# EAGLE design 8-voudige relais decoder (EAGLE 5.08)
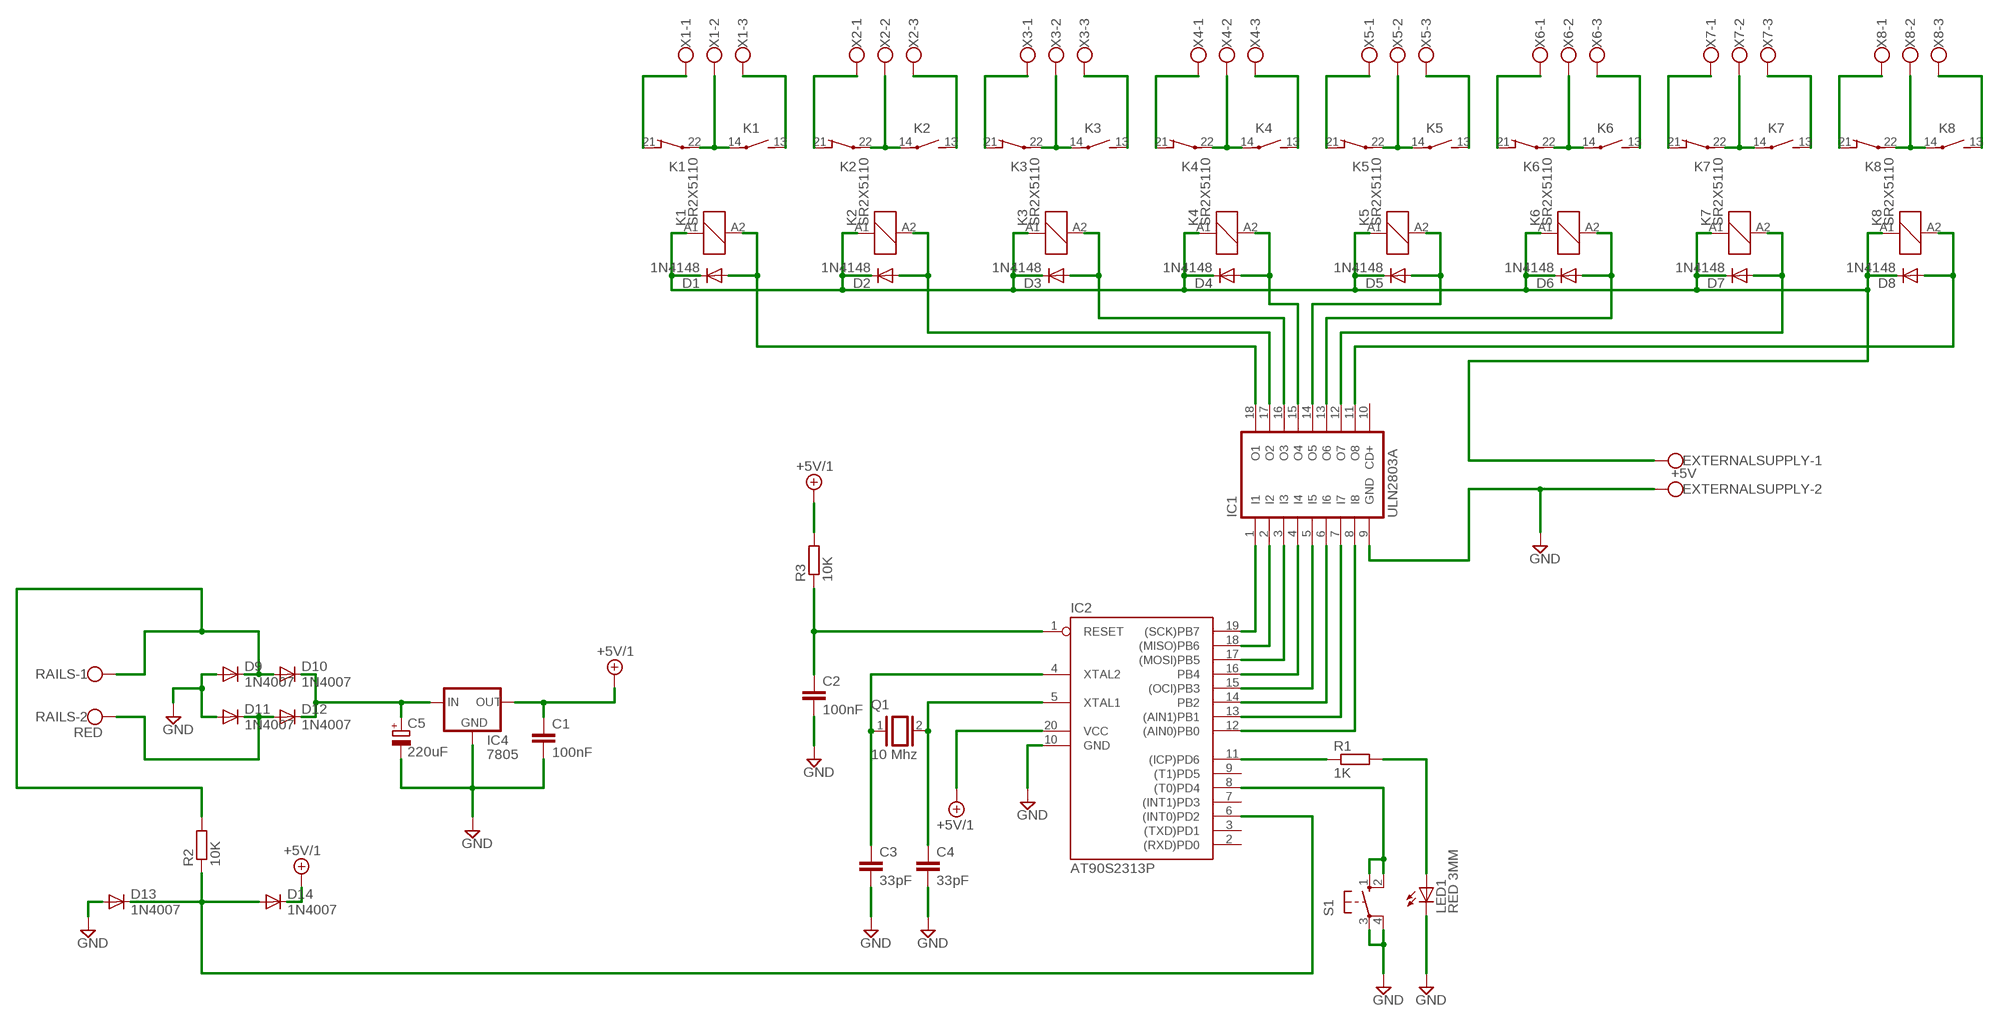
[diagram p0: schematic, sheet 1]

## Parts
C1  100nF  C-EU025-025X050  [C025-025X050]
C2  100nF  C-EU025-025X050  [C025-025X050]
C3  33pF  C-EU025-025X050  [C025-025X050]
C4  33pF  C-EU025-025X050  [C025-025X050]
C5  220uF  CPOL-EUTT6D6  [TT5D6]
D1  1N4148  1N4148DO35-7  [DO35-7]
D2  1N4148  1N4148DO35-7  [DO35-7]
D3  1N4148  1N4148DO35-7  [DO35-7]
D4  1N4148  1N4148DO35-7  [DO35-7]
D5  1N4148  1N4148DO35-7  [DO35-7]
D6  1N4148  1N4148DO35-7  [DO35-7]
D7  1N4148  1N4148DO35-7  [DO35-7]
D8  1N4148  1N4148DO35-7  [DO35-7]
D9  1N4007  1N4148DO35-10  [DO35-10]
D10  1N4007  1N4148DO35-10  [DO35-10]
D11  1N4007  1N4148DO35-10  [DO35-10]
D12  1N4007  1N4148DO35-10  [DO35-10]
D13  1N4007  1N4148DO35-10  [DO35-10]
D14  1N4007  1N4148DO35-10  [DO35-10]
EXTERNALSUPPLY  +5V  W237-102  [W237-102]
IC1  ULN2803A  [DIL18]
IC2  AT90S2313P  [DIL20]
IC4  7805  78XXL  [78XXL]
K1  SR2X5110  [SR2X]
K2  SR2X5110  [SR2X]
K3  SR2X5110  [SR2X]
K4  SR2X5110  [SR2X]
K5  SR2X5110  [SR2X]
K6  SR2X5110  [SR2X]
K7  SR2X5110  [SR2X]
K8  SR2X5110  [SR2X]
LED1  RED 3MM  LED3MM  [LED3MM]
Q1  10 Mhz  XTAL/S  [QS]
R1  1K  R-EU_0207/10  [0207/10]
R2  10K  R-EU_0207/10  [0207/10]
R3  10K  R-EU_0207/10  [0207/10]
RAILS  RED  W237-102  [W237-102]
S1  10-XX  [B3F-10XX]
X1  W237-103  [W237-103]
X2  W237-103  [W237-103]
X3  W237-103  [W237-103]
X4  W237-103  [W237-103]
X5  W237-103  [W237-103]
X6  W237-103  [W237-103]
X7  W237-103  [W237-103]
X8  W237-103  [W237-103]

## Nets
+5V/1: C1.1 D14.C IC2.20(VCC) IC4.OUT R3.2
GND: C1.2 C2.2 C3.2 C4.2 C5.- D9.A D11.A D13.A EXTERNALSUPPLY.2 IC1.9(GND) IC2.10(GND) IC4.GND LED1.K(C) S1.3(P) S1.4(P1)
N$1: D1.C D2.C D3.C D4.C D5.C D6.C D7.C D8.C EXTERNALSUPPLY.1 K1.A1 K2.A1 K3.A1 K4.A1 K5.A1 K6.A1 K7.A1 K8.A1
N$2: D1.A IC1.18(O1) K1.A2
N$3: K1.14(3:P) K1.22(2:P) X1.2
N$4: D2.A IC1.17(O2) K2.A2
N$5: K2.14(3:P) K2.22(2:P) X2.2
N$6: D3.A IC1.16(O3) K3.A2
N$7: K3.14(3:P) K3.22(2:P) X3.2
N$8: D4.A IC1.15(O4) K4.A2
N$9: K4.14(3:P) K4.22(2:P) X4.2
N$10: D5.A IC1.14(O5) K5.A2
N$11: K5.14(3:P) K5.22(2:P) X5.2
N$12: D6.A IC1.13(O6) K6.A2
N$13: K6.14(3:P) K6.22(2:P) X6.2
N$14: D7.A IC1.12(O7) K7.A2
N$15: K7.14(3:P) K7.22(2:P) X7.2
N$16: D8.A IC1.11(O8) K8.A2
N$17: K8.14(3:P) K8.22(2:P) X8.2
N$18: K1.21(2:O) X1.1
N$19: K1.13(3:S) X1.3
N$20: K2.21(2:O) X2.1
N$21: K2.13(3:S) X2.3
N$22: K3.21(2:O) X3.1
N$23: K3.13(3:S) X3.3
N$24: K4.21(2:O) X4.1
N$25: K4.13(3:S) X4.3
N$26: K5.21(2:O) X5.1
N$27: K5.13(3:S) X5.3
N$28: K6.21(2:O) X6.1
N$29: K6.13(3:S) X6.3
N$30: K7.21(2:O) X7.1
N$31: K7.13(3:S) X7.3
N$32: K8.21(2:O) X8.1
N$33: K8.13(3:S) X8.3
N$34: IC1.1(I1) IC2.19((SCK)PB7)
N$35: IC1.2(I2) IC2.18((MISO)PB6)
N$36: IC1.3(I3) IC2.17((MOSI)PB5)
N$37: IC1.4(I4) IC2.16(PB4)
N$38: IC1.5(I5) IC2.15((OCI)PB3)
N$39: IC1.6(I6) IC2.14(PB2)
N$40: IC1.7(I7) IC2.13((AIN1)PB1)
N$41: IC1.8(I8) IC2.12((AIN0)PB0)
N$42: IC2.8((T0)PD4) S1.1(S) S1.2(S1)
N$43: C4.1 IC2.5(XTAL1) Q1.2
N$44: IC2.11((ICP)PD6) R1.1
N$45: LED1.A R1.2
N$46: D13.C D14.A IC2.6((INT0)PD2) R2.1
N$47: C5.+ D10.C D12.C IC4.IN
N$48: D9.C D10.A R2.2 RAILS.1
N$49: D11.C D12.A RAILS.2
N$50: C3.1 IC2.4(XTAL2) Q1.1
N$51: C2.1 IC2.1(RESET) R3.1
Unconnected: IC1.10(CD+) IC2.2((RXD)PD0) IC2.3((TXD)PD1) IC2.7((INT1)PD3) IC2.9((T1)PD5)

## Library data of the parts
C1-C4 = rcl:C-EU: CAPACITOR, European symbol
C5 = rcl:CPOL-EU: POLARIZED CAPACITOR, European symbol
D1-D14 = diode:1N4148: DIODE
EXTERNALSUPPLY RAILS = con-wago-500:W237-102: WAGO SCREW CLAMP
IC1 = uln-udn:ULN2803A: DRIVER ARRAY
IC2 = atmel:AT90S2313: MICROCONTROLLER 2 Kbytes FLASH 128 bytes SRAM 128 bytes EEPROM UART
IC4 = v-reg:78XXL: VOLTAGE REGULATOR
K1-K8 = relay:SR2X5*: Safety Relay 2 pole 6 A SCHRACK Source: http://www.schrack.com/.. 5809.pdf
LED1 = led:LED: LED
Q1 = special:XTAL/S: CRYSTAL
R1-R3 = resistor:R-EU_: RESISTOR, European symbol
S1 = switch-omron:10-XX: OMRON SWITCH
X1-X8 = con-wago-500:W237-103: WAGO SCREW CLAMP

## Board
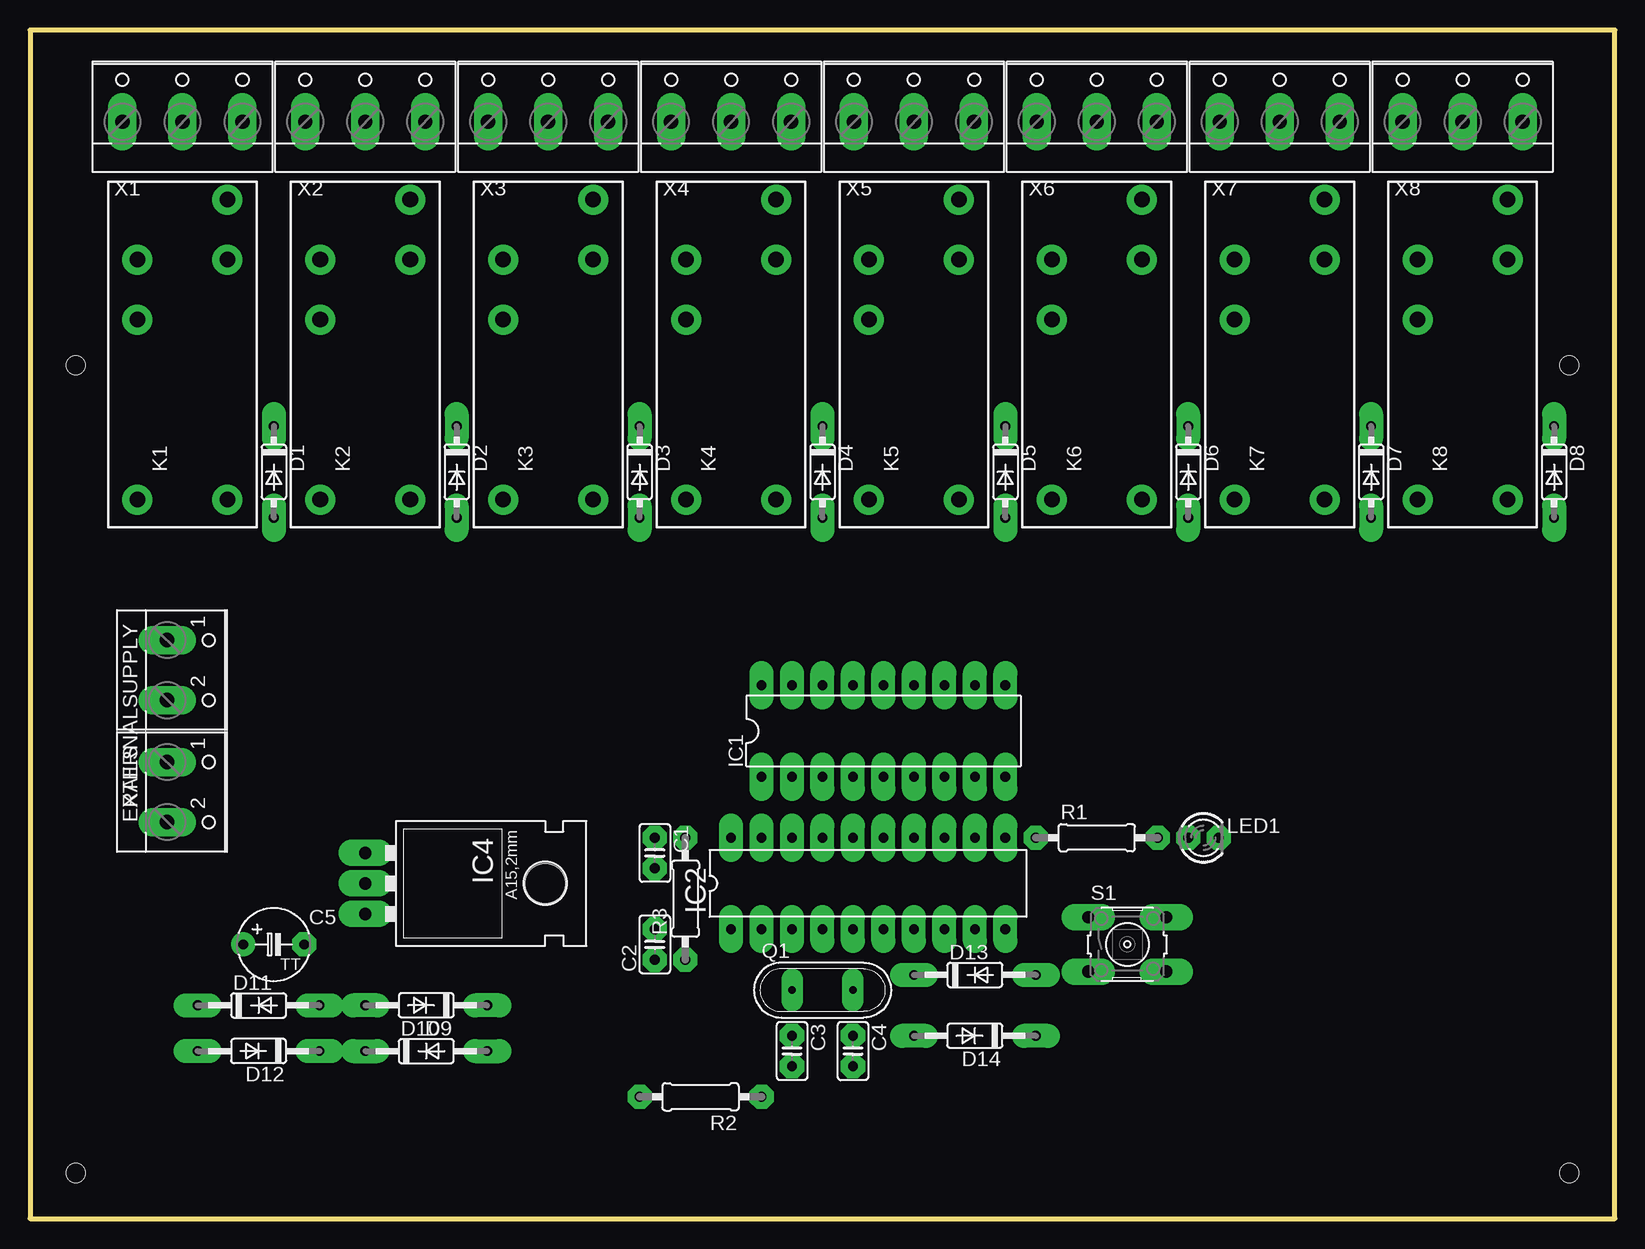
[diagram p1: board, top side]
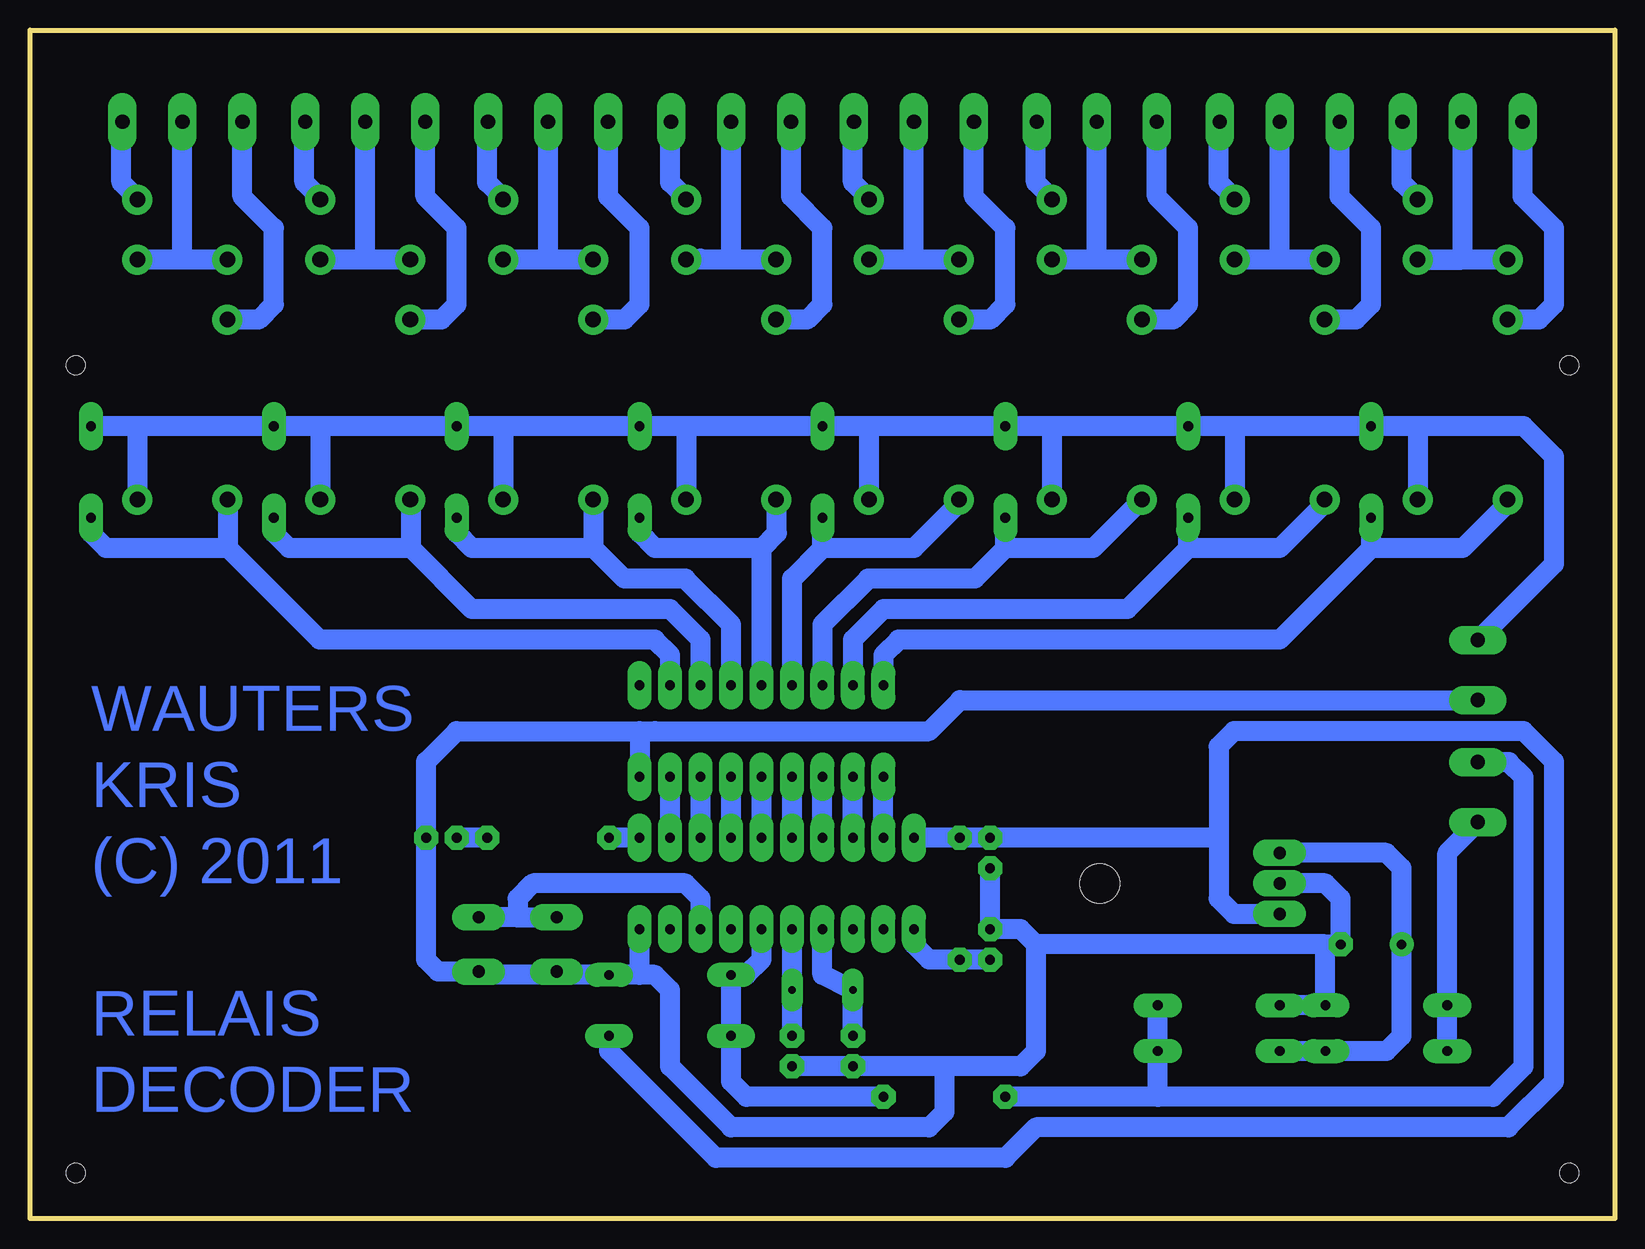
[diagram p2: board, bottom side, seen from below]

Size 132.08 x 99.06 mm. Coordinates in mm from the lower left corner, seen from the top.
Outline: 0,0 132.08,0 132.08,99.06 0,99.06 0,0
Copper layers (1*16): Top 1mm / dielectric 1.5mm / Bottom 1mm
Design rules "DRC settings middle": minimum track width 1.2mm, minimum drill 24mil, track to track 0.4mm, track to pad 0.4mm, pad to pad 0.4mm, via to via 0.4mm, smd to smd 8mil, copper to edge 0.5mm, drill to drill 0.5mm, minimum pad ring 0.6mm, minimum via ring 1mm, stop-mask expansion 4mil, vias tented up to drill 0mil, thermal gap 10mil
Holes 1.6 mm at 3.81,71.12 128.27,71.12 3.81,3.81 128.27,3.81

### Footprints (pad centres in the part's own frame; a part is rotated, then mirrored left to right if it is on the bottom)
C025-025X050 = drill 0.813 octagon: 1 -1.27,0; 2 1.27,0
TT5D6 = drill 0.813 round: + -2.54,0 | drill 0.813 octagon: - 2.54,0
DO35-7 = drill 0.813 long: A 3.81,0; C -3.81,0
DO35-10 = drill 0.813 long: A 5.08,0; C -5.08,0
W237-102 = drill 1.194 long: 1 -2.5,-1.27; 2 2.5,-1.27
DIL18 = drill 0.813 long: 1 -10.16,-3.81; 2 -7.62,-3.81; 3 -5.08,-3.81; 4 -2.54,-3.81; 5 0,-3.81; 6 2.54,-3.81; 7 5.08,-3.81; 8 7.62,-3.81; 9 10.16,-3.81; 10 10.16,3.81; 11 7.62,3.81; 12 5.08,3.81; 13 2.54,3.81; 14 0,3.81; 15 -2.54,3.81; 16 -5.08,3.81; 17 -7.62,3.81; 18 -10.16,3.81
DIL20 = drill 0.813 long: 1 -11.43,-3.81; 2 -8.89,-3.81; 3 -6.35,-3.81; 4 -3.81,-3.81; 5 -1.27,-3.81; 6 1.27,-3.81; 7 3.81,-3.81; 8 6.35,-3.81; 9 8.89,-3.81; 10 11.43,-3.81; 11 11.43,3.81; 12 8.89,3.81; 13 6.35,3.81; 14 3.81,3.81; 15 1.27,3.81; 16 -1.27,3.81; 17 -3.81,3.81; 18 -6.35,3.81; 19 -8.89,3.81; 20 -11.43,3.81
78XXL = drill 1.016 long: GND 0,-3.81; IN -2.54,-3.81; OUT 2.54,-3.81 | hole 3.302: 0,11.176
SR2X = drill 1.3 round: 13 12.54,-3.75; 14 7.54,-3.75; 21 2.54,3.75; 22 7.54,3.75; A1 -12.46,-3.75; A2 -12.46,3.75
LED3MM = drill 0.813 octagon: A -1.27,0; K 1.27,0
QS = drill 0.61 long: 1 -2.54,0; 2 2.54,0
0207/10 = drill 0.813 octagon: 1 -5.08,0; 2 5.08,0
B3F-10XX = drill 1.016 long: 1 -3.251,2.261; 2 3.251,2.261; 3 -3.251,-2.261; 4 3.251,-2.261
W237-103 = drill 1.194 long: 1 -5,-1.29; 2 0,-1.29; 3 5,-1.29

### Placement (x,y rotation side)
C1  52.07,30.48 270 top
C2  52.07,22.86 90 top
C3  63.5,13.97 270 top
C4  68.58,13.97 270 top
C5  20.32,22.86 0 top
D1  20.32,62.23 270 top
D2  35.56,62.23 270 top
D3  50.8,62.23 270 top
D4  66.04,62.23 270 top
D5  81.28,62.23 270 top
D6  96.52,62.23 270 top
D7  111.76,62.23 270 top
D8  127,62.23 270 top
D9  33.02,17.78 180 top
D10  33.02,13.97 0 top
D11  19.05,17.78 0 top
D12  19.05,13.97 180 top
D13  78.74,20.32 0 top
D14  78.74,15.24 180 top
EXTERNALSUPPLY  12.7,45.72 270 top
IC1  71.12,40.64 0 top
IC2  69.85,27.94 0 top
IC4  31.75,27.94 270 top
K1  12.7,72.39 90 top
K2  27.94,72.39 90 top
K3  43.18,72.39 90 top
K4  58.42,72.39 90 top
K5  73.66,72.39 90 top
K6  88.9,72.39 90 top
K7  104.14,72.39 90 top
K8  119.38,72.39 90 top
LED1  97.79,31.75 0 top
Q1  66.04,19.05 0 top
R1  88.9,31.75 0 top
R2  55.88,10.16 180 top
R3  54.61,26.67 90 top
RAILS  12.7,35.56 270 top
S1  91.44,22.86 0 top
X1  12.7,92.71 0 top
X2  27.94,92.71 0 top
X3  43.18,92.71 0 top
X4  58.42,92.71 0 top
X5  73.66,92.71 0 top
X6  88.9,92.71 0 top
X7  104.14,92.71 0 top
X8  119.38,92.71 0 top

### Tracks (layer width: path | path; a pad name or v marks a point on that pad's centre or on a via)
+5V/1
  Bottom 1.676: IC2.20 R3.2 C1.1 33.02,31.75 | IC4.OUT 31.75,25.4 33.02,26.67 33.02,31.75 | 33.02,31.75 33.02,39.37 31.75,40.64 7.62,40.64 5.08,38.1 5.08,11.43 8.89,7.62 48.26,7.62 50.8,5.08 74.93,5.08 83.82,13.97 D14.C
GND
  Bottom 1.676: IC4.GND 24.13,27.94 22.86,26.67 C5.- 24.13,22.86 | C4.2 C3.2 55.88,12.7 | C1.2 C2.2 49.53,24.13 48.26,22.86 | 87.63,20.32 D13.A 81.28,20.32 | 87.63,20.32 95.25,20.32 94.26,20.32 93.98,20.6 S1.4 98.07,20.6 99.06,21.59 LED1.K 99.06,38.1 96.52,40.64 81.28,40.64 | 81.28,20.32 80.01,20.32 78.74,19.05 78.74,12.7 73.66,7.62 57.15,7.62 55.88,8.89 55.88,12.7 | EXTERNALSUPPLY.2 54.57,43.22 57.15,40.64 80.01,40.64 81.28,40.64 | 81.28,40.64 IC1.9 | 55.88,12.7 49.53,12.7 48.26,13.97 48.26,22.86 | 81.28,20.32 IC2.10 | 24.13,22.86 48.26,22.86 | D9.A D11.A 24.13,22.86 | S1.3 87.91,20.6 87.63,20.32
N$1
  Bottom 1.676: 31.75,66.04 D1.C 17.78,66.04 16.51,66.04 | 31.75,66.04 D2.C 46.99,66.04 | 46.99,66.04 D3.C 62.23,66.04 | 62.23,66.04 D4.C 77.47,66.04 | 77.47,66.04 D5.C 92.71,66.04 | 92.71,66.04 D6.C 107.95,66.04 | 107.95,66.04 D7.C 123.19,66.04 | 123.19,66.04 D8.C | K2.A1 31.69,65.98 31.75,66.04 | K3.A1 46.93,65.98 46.99,66.04 | K4.A1 62.17,65.98 62.23,66.04 | K5.A1 77.41,65.98 77.47,66.04 | K6.A1 92.65,65.98 92.71,66.04 | K7.A1 107.89,65.98 107.95,66.04 | K8.A1 123.13,65.98 123.19,66.04 | 16.51,66.04 7.62,66.04 5.08,63.5 5.08,54.57 EXTERNALSUPPLY.1 | K1.A1 16.45,65.98 16.51,66.04
N$2
  Bottom 1.676: IC1.18 60.96,46.99 59.69,48.26 27.94,48.26 20.32,55.88 | 20.32,55.88 D1.A | K1.A2 8.95,59.63 12.7,55.88 20.32,55.88
N$3
  Bottom 1.676: K1.22 K1.14 12.78,79.93 12.7,80.01 X1.2
N$4
  Bottom 1.676: IC1.17 63.5,48.26 60.96,50.8 40.64,50.8 35.56,55.88 | 35.56,55.88 35.56,57.15 D2.A | K2.A2 24.19,59.63 27.94,55.88 35.56,55.88
N$5
  Bottom 1.676: K2.22 27.94,79.93 | 27.94,79.93 K2.14 | 27.94,79.93 X2.2
N$6
  Bottom 1.676: 50.8,57.15 D3.A 50.8,55.88 | K3.A2 43.48,55.88 50.8,55.88 | IC1.16 66.04,49.53 62.23,53.34 53.34,53.34 50.8,55.88
N$7
  Bottom 1.676: K3.22 43.18,79.93 | 43.18,79.93 K3.14 | 43.18,79.93 X3.2
N$8
  Bottom 1.676: 66.04,55.88 D4.A | K4.A2 54.67,59.63 58.42,55.88 66.04,55.88 | IC1.15 68.58,53.34 66.04,55.88
N$9
  Bottom 1.676: K4.22 58.42,79.93 | 58.42,79.93 K4.14 | 58.42,79.93 X4.2
N$10
  Bottom 1.676: 69.85,59.87 K5.A2 69.85,59.87 | D5.A 81.28,57.15 80.01,55.88 71.12,55.88 | 71.12,55.88 69.85,57.15 69.85,59.87 | IC1.14 71.12,55.88
N$11
  Bottom 1.676: K5.22 73.66,79.93 | 73.66,79.93 76.12,79.93 76.2,80.01 76.28,79.93 K5.14 | 73.66,79.93 X5.2
N$12
  Bottom 1.676: D6.A 96.52,57.15 95.25,55.88 89.2,55.88 85.09,55.88 | IC1.13 73.66,49.53 77.47,53.34 82.55,53.34 85.09,55.88 | 85.09,55.88 85.09,59.87 K6.A2
N$13
  Bottom 1.676: K6.22 88.9,79.93 | 88.9,79.93 K6.14 | 88.9,79.93 X6.2
N$14
  Bottom 1.676: D7.A 111.76,57.15 110.49,55.88 104.44,55.88 100.33,55.88 | IC1.12 76.2,48.26 78.74,50.8 95.25,50.8 100.33,55.88 | 100.33,55.88 100.33,59.87 K7.A2
N$15
  Bottom 1.676: K7.22 104.14,79.93 | 104.14,79.93 K7.14 | 104.14,79.93 X7.2
N$16
  Bottom 1.676: D8.A 127,57.15 125.73,55.88 119.68,55.88 115.57,55.88 | IC1.11 78.74,46.99 80.01,48.26 107.95,48.26 115.57,55.88 | 115.57,55.88 115.57,59.87 K8.A2
N$17
  Bottom 1.676: K8.22 119.38,79.93 | 119.38,79.93 K8.14 | 119.38,79.93 X8.2
N$18
  Bottom 1.676: X1.1 7.7,85.17 5.08,82.55 5.08,76.2 6.35,74.93 K1.21
N$19
  Bottom 1.676: K1.13 16.45,85.03 17.78,86.36 17.78,91.34 X1.3
N$20
  Bottom 1.676: X2.1 22.94,85.17 20.32,82.55 20.32,78.8 20.32,76.2 21.59,74.93 K2.21
N$21
  Bottom 1.676: K2.13 31.69,85.03 33.02,86.36 33.02,91.34 X2.3
N$22
  Bottom 1.676: X3.1 38.18,85.17 35.56,82.55 35.56,76.2 36.83,74.93 K3.21
N$23
  Bottom 1.676: K3.13 46.93,85.03 48.26,86.36 48.26,91.34 X3.3
N$24
  Bottom 1.676: X4.1 53.42,85.17 50.8,82.55 50.8,76.2 52.07,74.93 K4.21
N$25
  Bottom 1.676: K4.13 62.17,85.03 63.5,86.36 63.5,91.34 X4.3
N$26
  Bottom 1.676: X5.1 68.66,85.17 66.04,82.55 66.04,76.2 67.31,74.93 K5.21
N$27
  Bottom 1.676: K5.13 77.41,85.03 78.74,86.36 78.74,91.34 X5.3
N$28
  Bottom 1.676: X6.1 83.9,85.17 81.28,82.55 81.28,76.2 82.55,74.93 K6.21
N$29
  Bottom 1.676: K6.13 92.65,85.03 93.98,86.36 93.98,91.34 X6.3
N$30
  Bottom 1.676: X7.1 99.14,85.17 96.52,82.55 96.52,76.2 97.79,74.93 K7.21
N$31
  Bottom 1.676: K7.13 107.89,85.03 109.22,86.36 109.22,91.34 X7.3
N$32
  Bottom 1.676: X8.1 114.38,85.17 111.76,82.55 111.76,76.2 113.03,74.93 K8.21
N$33
  Bottom 1.676: K8.13 123.13,85.03 124.46,86.36 124.46,91.34 X8.3
N$34
  Bottom 1.676: IC2.19 IC1.1
N$35
  Bottom 1.676: IC2.18 IC1.2
N$36
  Bottom 1.676: IC2.17 IC1.3
N$37
  Bottom 1.676: IC2.16 IC1.4
N$38
  Bottom 1.676: IC2.15 IC1.5
N$39
  Bottom 1.676: IC2.14 IC1.6
N$40
  Bottom 1.676: IC2.13 IC1.7
N$41
  Bottom 1.676: IC2.12 IC1.8
N$42
  Bottom 1.676: 91.44,25.12 S1.1 | 91.44,25.12 S1.2 | IC2.8 76.2,26.67 77.47,27.94 90.17,27.94 91.44,26.67 91.44,25.12
N$43
  Bottom 1.676: IC2.5 Q1.2 C4.1
N$44
  Bottom 1.676: IC2.11 R1.1
N$45
  Bottom 1.676: R1.2 LED1.A
N$46
  Bottom 1.676: R2.1 72.39,10.16 73.66,11.43 D14.A D13.C 72.39,20.32 71.12,21.59 IC2.6
N$47
  Bottom 1.676: D12.C 19.05,13.97 17.78,15.24 C5.+ 17.78,29.21 19.05,30.48 IC4.IN | D12.C D10.C D12.C
N$48
  Bottom 1.676: D9.C D10.A 38.1,10.16 | 38.1,10.16 R2.2 | RAILS.1 8.85,38.06 7.62,36.83 7.62,12.7 10.16,10.16 38.1,10.16
N$49
  Bottom 1.676: D12.A D11.C 13.97,30.48 11.43,33.02 RAILS.2
N$50
  Bottom 1.676: IC2.4 66.04,20.32 Q1.1 C3.1
N$51
  Bottom 1.676: IC2.1 58.42,22.86 57.15,21.59 R3.1 C2.1

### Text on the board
Bottom: WAUTERS | KRIS | (C) 2011 | RELAIS | DECODER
